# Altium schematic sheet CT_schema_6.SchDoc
size 479 x 328 mm
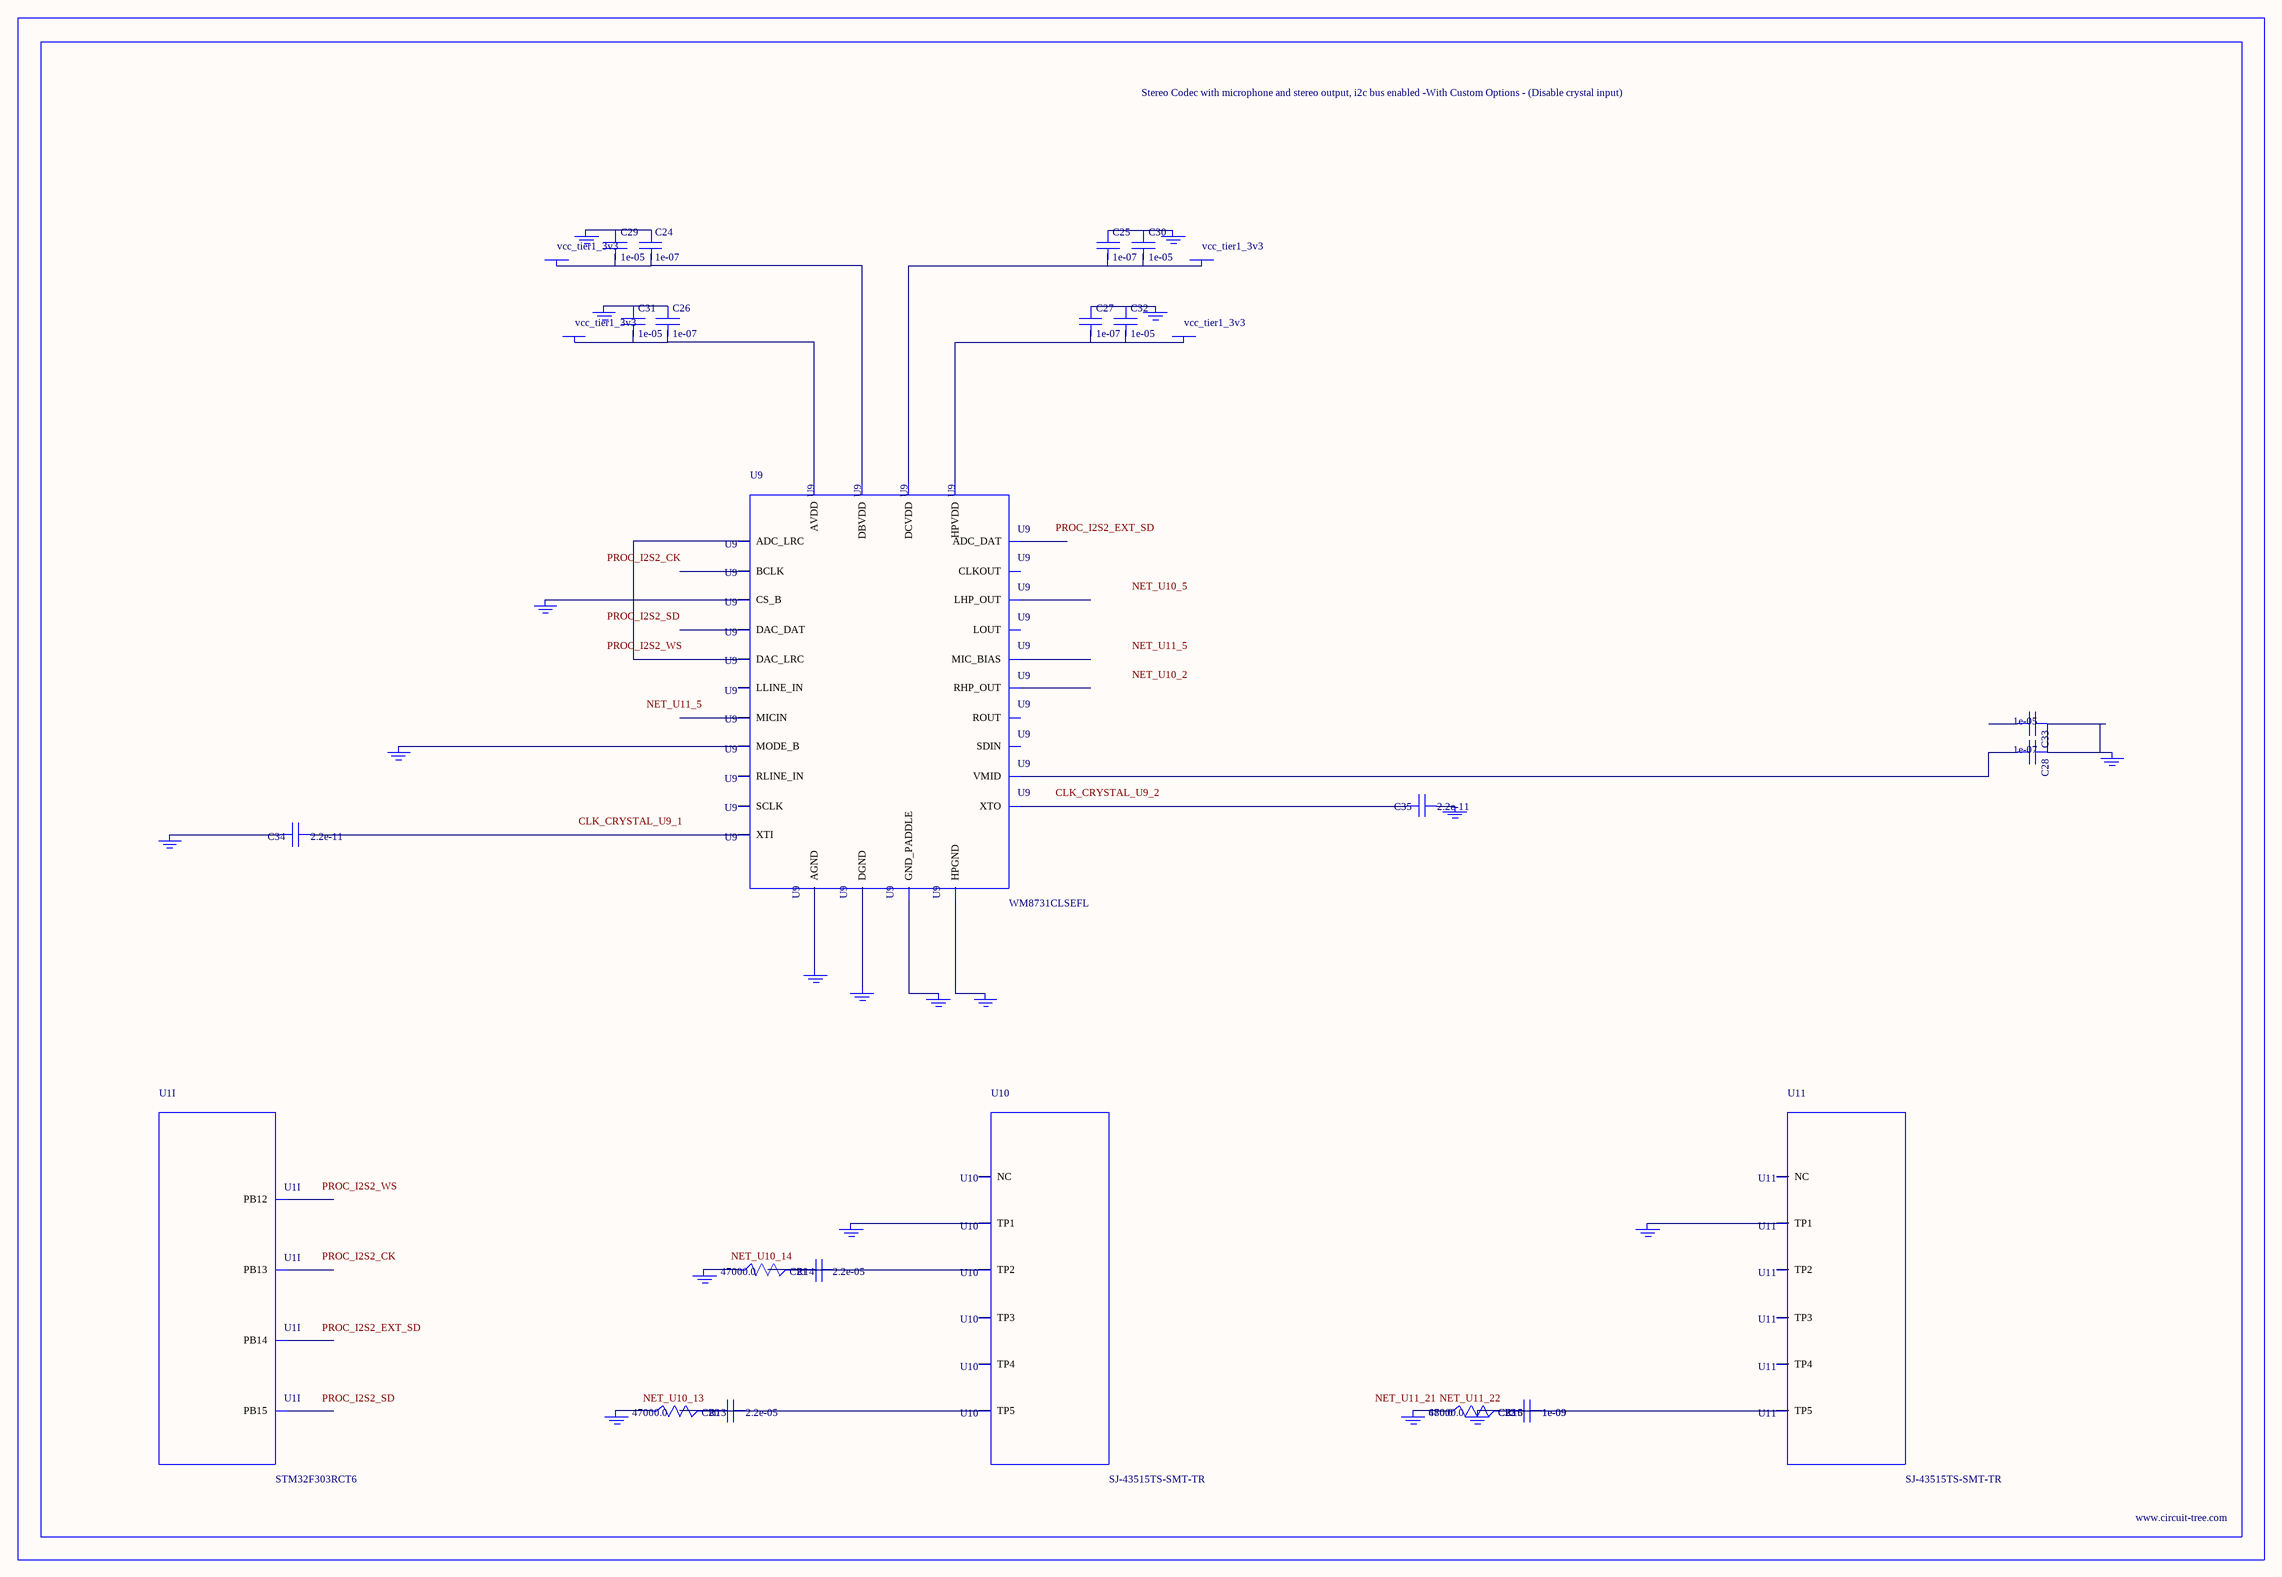
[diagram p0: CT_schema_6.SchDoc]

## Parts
BORDER5  (no value)
C20  2.2e-05  [C1210]
C21  2.2e-05  [C1210]
C22  1e-09  [C0402]
C23  1e-09  [C0402]
C24  1e-07  [C0402]
C25  1e-07  [C0402]
C26  1e-07  [C0402]
C27  1e-07  [C0402]
C28  1e-07  [C0402]
C29  1e-05  [C0805]
C30  1e-05  [C0805]
C31  1e-05  [C0805]
C32  1e-05  [C0805]
C33  1e-05  [C0805]
C34  2.2e-11  [C0402]
C35  2.2e-11  [C0402]
GND_INSTANCE_5_0  (no value)
GND_INSTANCE_5_1  (no value)
GND_INSTANCE_5_2  (no value)
GND_INSTANCE_5_3  (no value)
GND_INSTANCE_5_4  (no value)
GND_INSTANCE_5_5  (no value)
GND_INSTANCE_5_6  (no value)
GND_INSTANCE_5_7  (no value)
GND_INSTANCE_5_8  (no value)
GND_INSTANCE_5_9  (no value)
GND_INSTANCE_5_10  (no value)
GND_INSTANCE_5_11  (no value)
GND_INSTANCE_5_12  (no value)
GND_INSTANCE_5_13  (no value)
GND_INSTANCE_5_14  (no value)
GND_INSTANCE_5_15  (no value)
GND_INSTANCE_5_16  (no value)
GND_INSTANCE_5_17  (no value)
GND_INSTANCE_5_18  (no value)
POWER_INSTANCE_5_0  vcc_tier1_3v3
POWER_INSTANCE_5_1  vcc_tier1_3v3
POWER_INSTANCE_5_2  vcc_tier1_3v3
POWER_INSTANCE_5_3  vcc_tier1_3v3
R13  47000.0  [R0603]
R14  47000.0  [R0603]
R15  47000.0  [R0603]
R16  680.0  [R0603]
U1  STM32F303RCT6  [LQFP64]  (part I of 9)
U9  WM8731CLSEFL  [QFN-28]
U10  SJ-43515TS-SMT-TR  [SJ-43515TS-SMT-TR]
U11  SJ-43515TS-SMT-TR  [SJ-43515TS-SMT-TR]

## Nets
NetC20_1: C20.1 C20.2 R13.2 U10.5(TP5)
NetC21_1: C21.1 C21.2 R14.2 U10.2(TP2)
NetC22_1: C22.1 C22.2 C23.1 C23.2 GND_INSTANCE_5_18.0(GND) R15.2 R16.2 U11.5(TP5)
NetC24_1: C24.1 C29.1 GND_INSTANCE_5_3.0(GND)
NetC24_2: C24.2 C29.2 POWER_INSTANCE_5_1.0(PWR) U9.5(DBVDD)
NetC25_1: C25.1 C30.1 GND_INSTANCE_5_2.0(GND)
NetC25_2: C25.2 C30.2 POWER_INSTANCE_5_0.0(PWR) U9.3(DCVDD)
NetC26_1: C26.1 C31.1 GND_INSTANCE_5_6.0(GND)
NetC26_2: C26.2 C31.2 POWER_INSTANCE_5_3.0(PWR) U9.18(AVDD)
NetC27_1: C27.1 C32.1 GND_INSTANCE_5_4.0(GND)
NetC27_2: C27.2 C32.2 POWER_INSTANCE_5_2.0(PWR) U9.12(HPVDD)
NetC28_1: C28.1 C33.1 GND_INSTANCE_5_7.0(GND)
NetC28_2: C28.2 U9.20(VMID)
NetC34_1: C34.1 U9.1(XTI)
NetC34_2: C34.2 GND_INSTANCE_5_0.0(GND)
NetC35_1: C35.1 GND_INSTANCE_5_1.0(GND)
NetC35_2: C35.2 U9.2(XTO)
NetGND_INSTANCE_5_5_0: GND_INSTANCE_5_5.0(GND) U9.15(HPGND)
NetGND_INSTANCE_5_8_0: GND_INSTANCE_5_8.0(GND) U9.25(MODE_B)
NetGND_INSTANCE_5_9_0: GND_INSTANCE_5_9.0(GND) U9.26(CS_B)
NetGND_INSTANCE_5_10_0: GND_INSTANCE_5_10.0(GND) U9.29(GND_PADDLE)
NetGND_INSTANCE_5_11_0: GND_INSTANCE_5_11.0(GND) U9.4(DGND)
NetGND_INSTANCE_5_12_0: GND_INSTANCE_5_12.0(GND) U9.19(AGND)
NetGND_INSTANCE_5_13_0: GND_INSTANCE_5_13.0(GND) U10.1(TP1)
NetGND_INSTANCE_5_14_0: GND_INSTANCE_5_14.0(GND) R14.1
NetGND_INSTANCE_5_15_0: GND_INSTANCE_5_15.0(GND) R13.1
NetGND_INSTANCE_5_16_0: GND_INSTANCE_5_16.0(GND) U11.1(TP1)
NetGND_INSTANCE_5_17_0: GND_INSTANCE_5_17.0(GND) R15.1 R16.1
NetU9_9: U9.9(DAC_LRC) U9.11(ADC_LRC)

Not connected (* = marked no-connect by the designer): C33 2; U1 33(PB12) 34(PB13) 35(PB14) 36(PB15); U9 6(CLKOUT) 7(BCLK) 8(DAC_DAT) 10(ADC_DAT) 13(LHP_OUT) 14(RHP_OUT) 16(LOUT) 17(ROUT) 21(MIC_BIAS) 22(MICIN) 23(RLINE_IN) 24(LLINE_IN) 27(SDIN) 28(SCLK); U10 3(TP3) 4(TP4) 6(NC); U11 2(TP2) 3(TP3) 4(TP4) 6(NC)

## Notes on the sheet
- Labels drawn without touching a wire or pin: CLK_CRYSTAL_U9_1, CLK_CRYSTAL_U9_2, NET_U10_2, NET_U10_5, NET_U10_13, NET_U10_14, NET_U11_5, NET_U11_21, NET_U11_22, PROC_I2S2_CK, PROC_I2S2_EXT_SD, PROC_I2S2_SD, PROC_I2S2_WS

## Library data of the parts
BORDER5 = BORDER_PAGE5
C20 C21 = C1210C224K5RACTU
C22 C23 = C0402C102K3RAC
C24-C28 = C0402C104K3RACTU
C29-C33 = C0805C106K8RACTU
C34 C35 = C0402C220K3RAC
GND_INSTANCE_5_0-GND_INSTANCE_5_18 = GND
POWER_INSTANCE_5_0-POWER_INSTANCE_5_3 = PWR
R13-R15 = RC0603JR-0747KL
R16 = RC0603JR-07680RL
